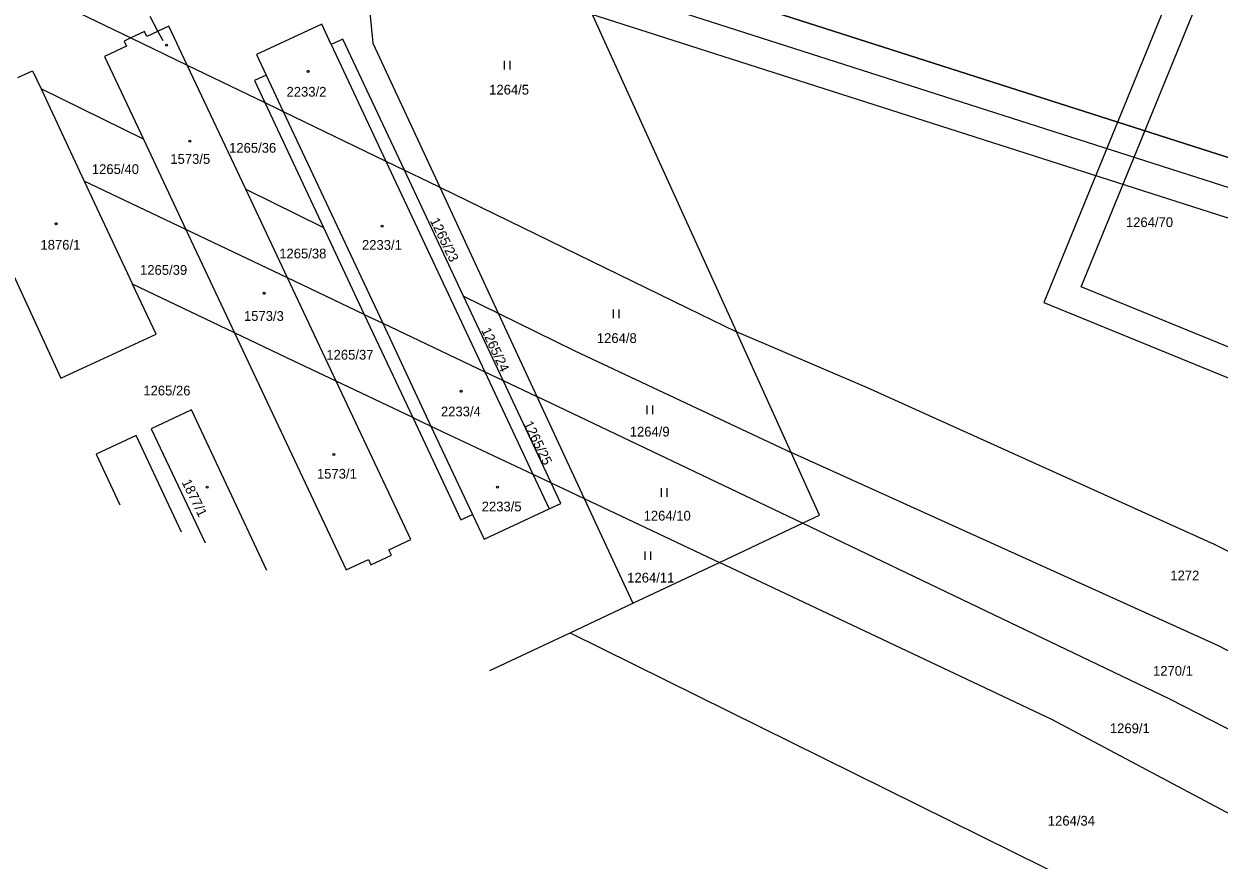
# Model space of a CAD drawing. Extents: x -779330 to -774454, y -1144748 to -1142831.
# Drawn here: x -777170.1 to -776961.8, y -1144133.7 to -1143987.9 of the extents above; entities that cross this region are included whole.
import ezdxf

# ---------------------------------------------------------------- set-up
doc = ezdxf.new("R2010")
doc.units = 0
for name, color, linetype in [('Hranice parcel', 7, 'Continuous'), ('Parcelní čísla', 7, 'Continuous'), ('Pop  PČ popisy', 7, 'Continuous'), ('Vnitřní kresba', 7, 'Continuous'), ('Vrstva 1', 7, 'Continuous'), ('Značky budov', 7, 'Continuous'), ('Značky kultur', 7, 'Continuous')]:
    doc.layers.add(name, color=color, linetype=linetype)

msp = doc.modelspace()

# ---------------------------------------------------------------- linework, layer by layer
at = {"layer": 'Hranice parcel'}
for p, q in [((-777087.76, -1143949.47), (-777045.94, -1144041.58)), ((-777151.49, -1143990.35), (-777141.63, -1143995.11)), ((-777141.63, -1143995.11), (-777128.13, -1144001.62)), ((-777131.43, -1144016.75), (-777141.63, -1143995.11)), ((-777149.29, -1144007.99), (-777167.13, -1143999.23)), ((-777167.13, -1143999.23), (-777159.6, -1144015.3)), ((-777128.13, -1144001.62), (-777117.9, -1144023.39)), ((-777149.29, -1144007.99), (-777141.88, -1144023.74)), ((-777093.49, -1144035.37), (-777103.79, -1144013.4)), ((-777141.88, -1144023.74), (-777159.6, -1144015.3)), ((-777159.6, -1144015.3), (-777151.17, -1144033.27)), ((-777131.43, -1144016.75), (-777117.9, -1144023.39)), ((-777124.16, -1144032.18), (-777131.43, -1144016.75)), ((-777097.63, -1144016.39), (-777087.44, -1144038.34)), ((-777141.88, -1144023.74), (-777133.39, -1144041.77)), ((-777124.16, -1144032.18), (-777141.88, -1144023.74)), ((-777117.9, -1144023.39), (-777110.78, -1144038.56)), ((-777110.78, -1144038.56), (-777124.16, -1144032.18)), ((-777115.67, -1144050.19), (-777124.16, -1144032.18)), ((-777133.39, -1144041.77), (-777151.17, -1144033.27)), ((-777093.49, -1144035.37), (-777087.44, -1144038.34)), ((-777086.6, -1144050.07), (-777093.49, -1144035.37)), ((-777087.44, -1144038.34), (-777080.69, -1144052.88)), ((-777110.78, -1144038.56), (-777102.35, -1144056.49)), ((-777036.4, -1144062.59), (-777045.94, -1144041.58)), ((-777102.35, -1144056.49), (-777115.67, -1144050.19)), ((-777078.24, -1144067.9), (-777086.6, -1144050.07)), ((-777086.6, -1144050.07), (-777080.69, -1144052.88)), ((-777034.39, -1144074.95), (-777080.69, -1144052.88)), ((-777080.69, -1144052.88), (-777072.46, -1144070.64)), ((-777078.24, -1144067.9), (-777072.46, -1144070.64)), ((-777072.46, -1144070.64), (-777048.9, -1144081.78)), ((-777072.46, -1144070.64), (-777063.99, -1144088.88)), ((-777048.9, -1144081.78), (-777034.39, -1144074.95)), ((-777063.99, -1144088.88), (-777048.9, -1144081.78)), ((-777074.93, -1144094.03), (-777063.99, -1144088.88)), ((-777088.89, -1144100.6), (-777074.93, -1144094.03))]:
    msp.add_line(p, q, dxfattribs=at)
for points in [[(-777242.24, -1143946.21), (-777233.61, -1143950.34), (-777182.11, -1143975.59), (-777151.49, -1143990.35)], [(-777093.52, -1143952.82), (-777109.82, -1143985.95), (-777109.29, -1143991.28), (-777097.63, -1144016.39)], [(-777141.63, -1143995.11), (-777144.83, -1143988.32), (-777148.68, -1143990.13), (-777149.1, -1143989.23), (-777151.49, -1143990.35)], [(-777103.79, -1144013.4), (-777114.5, -1143990.57), (-777116.54, -1143991.53), (-777118.21, -1143987.96), (-777129.57, -1143993.28), (-777127.9, -1143996.84), (-777129.93, -1143997.79), (-777128.13, -1144001.62)], [(-777151.49, -1143990.35), (-777152.65, -1143990.9), (-777152.22, -1143991.8), (-777156.06, -1143993.61), (-777149.29, -1144007.99)], [(-777171.18, -1143997.24), (-777168.61, -1143996.07), (-777167.13, -1143999.23)], [(-777128.13, -1144001.62), (-777125.96, -1144002.66), (-777124.93, -1144003.16), (-777107.02, -1144011.84), (-777103.79, -1144013.4)], [(-777103.79, -1144013.4), (-777099.68, -1144015.4), (-777097.63, -1144016.39)], [(-777097.63, -1144016.39), (-777054.51, -1144037.4), (-777045.94, -1144041.58)], [(-777176.95, -1144020.96), (-777163.68, -1144049.68), (-777147.08, -1144042), (-777151.17, -1144033.27)], [(-777087.44, -1144038.34), (-777074.06, -1144044.91), (-777036.4, -1144062.59)], [(-777110.78, -1144038.56), (-777107.58, -1144040.08), (-777089.79, -1144048.55), (-777086.6, -1144050.07)], [(-777115.67, -1144050.19), (-777124.3, -1144046.11), (-777133.39, -1144041.77)], [(-777133.39, -1144041.77), (-777113.94, -1144083.08), (-777110.04, -1144081.26), (-777109.62, -1144082.17), (-777106.05, -1144080.5), (-777106.48, -1144079.59), (-777102.66, -1144077.8), (-777115.67, -1144050.19)], [(-776908.05, -1144105.74), (-776962.58, -1144078.67), (-777023.09, -1144051.34), (-777045.94, -1144041.58)], [(-777127.79, -1144083.17), (-777140.89, -1144055.19), (-777147.92, -1144058.49), (-777138.54, -1144078.35)], [(-777102.35, -1144056.49), (-777099.16, -1144058), (-777081.43, -1144066.39), (-777078.24, -1144067.9)], [(-777102.35, -1144056.49), (-777093.95, -1144074.37), (-777091.92, -1144073.41), (-777089.88, -1144077.75), (-777078.58, -1144072.46), (-777076.55, -1144071.5), (-777078.24, -1144067.9)], [(-777142.67, -1144076.5), (-777150.56, -1144059.63), (-777157.5, -1144062.89), (-777153.38, -1144071.71)], [(-777034.39, -1144074.95), (-777031.42, -1144073.55), (-777036.4, -1144062.59)], [(-776898.22, -1144129.38), (-776961.92, -1144096.33), (-777036.4, -1144062.59)], [(-776903.59, -1144139.82), (-776970.41, -1144105.59), (-777034.39, -1144074.95)], [(-776910.86, -1144151.74), (-776990.98, -1144109.17), (-777048.9, -1144081.78)], [(-777074.93, -1144094.03), (-776915.07, -1144173.12), (-776914.76, -1144172.32)]]:
    msp.add_lwpolyline(points, dxfattribs=at)
at = {"layer": 'Pop  PČ popisy'}
for p, q in [((-777146.69, -1143989.28), (-777148.1, -1143986.63)), ((-777145.84, -1143990.86), (-777146.69, -1143989.28))]:
    msp.add_line(p, q, dxfattribs=at)
at = {"layer": 'Vnitřní kresba'}
for p, q in [((-777116.54, -1143991.53), (-777107.02, -1144011.84)), ((-777127.9, -1143996.84), (-777124.93, -1144003.16)), ((-777124.93, -1144003.16), (-777107.58, -1144040.08)), ((-777107.02, -1144011.84), (-777089.79, -1144048.55)), ((-777107.58, -1144040.08), (-777099.16, -1144058)), ((-777089.79, -1144048.55), (-777081.43, -1144066.39)), ((-777099.16, -1144058), (-777091.92, -1144073.41)), ((-777081.43, -1144066.39), (-777078.58, -1144072.46))]:
    msp.add_line(p, q, dxfattribs=at)
at = {"layer": 'Vrstva 1'}
for points in [[(-776606.88, -1143822.95), (-777806.9, -1143438.86), (-777897.43, -1143721.71), (-776697.42, -1144105.81)], [(-776700.65, -1144099.52), (-777891.15, -1143718.47), (-777803.66, -1143445.14), (-776613.17, -1143826.19)], [(-776619.45, -1143829.42), (-777605.19, -1143513.91), (-777689.63, -1143777.73), (-776703.89, -1144093.24)], [(-776703.89, -1144093.24), (-777689.63, -1143777.73), (-777605.19, -1143513.91), (-776619.45, -1143829.42)], [(-775713.68, -1144238.31), (-776879.99, -1143761.57), (-776992.36, -1144036.48), (-775826.05, -1144513.22)], [(-775828.78, -1144506.7), (-776985.84, -1144033.74), (-776877.25, -1143768.09), (-775720.2, -1144241.05)]]:
    msp.add_lwpolyline(points, close=True, dxfattribs=at)
at = {"layer": 'Značky budov'}
for centre in [(-777145.26, -1143991.64), (-777120.57, -1143996.19), (-777141.17, -1144008.34), (-777164.48, -1144022.74), (-777107.69, -1144023.16), (-777128.24, -1144034.87), (-777093.9, -1144051.95), (-777116.1, -1144062.96), (-777138.16, -1144068.65), (-777087.55, -1144068.67)]:
    msp.add_circle(centre, 0.175, dxfattribs=at)
at = {"layer": 'Značky kultur'}
for p, q in [((-777086.37, -1143995.84), (-777086.37, -1143994.34)), ((-777085.37, -1143995.84), (-777085.37, -1143994.34)), ((-777067.34, -1144039.19), (-777067.34, -1144037.69)), ((-777066.34, -1144039.19), (-777066.34, -1144037.69)), ((-777061.51, -1144055.92), (-777061.51, -1144054.42)), ((-777060.51, -1144055.92), (-777060.51, -1144054.42)), ((-777058.97, -1144070.35), (-777058.97, -1144068.85)), ((-777057.97, -1144070.35), (-777057.97, -1144068.85)), ((-777061.84, -1144081.35), (-777061.84, -1144079.85)), ((-777060.84, -1144081.35), (-777060.84, -1144079.85))]:
    msp.add_line(p, q, dxfattribs=at)

# ---------------------------------------------------------------- texts
at = {"layer": 'Parcelní čísla'}
for s, p in [('2233/2', (-777124.34, -1144000.6)), ('1264/5', (-777089.02, -1144000.23)), ('1265/36', (-777134.35, -1144010.37)), ('1573/5', (-777144.59, -1144012.31)), ('1265/40', (-777158.27, -1144014.08)), ('1264/70', (-776978.04, -1144023.33)), ('1876/1', (-777167.23, -1144027.27)), ('2233/1', (-777111.19, -1144027.29)), ('1265/38', (-777125.61, -1144028.79)), ('1265/39', (-777149.87, -1144031.65)), ('1573/3', (-777131.76, -1144039.67)), ('1264/8', (-777070.25, -1144043.53)), ('1265/37', (-777117.4, -1144046.43)), ('1265/26', (-777149.3, -1144052.67)), ('2233/4', (-777097.43, -1144056.32)), ('1264/9', (-777064.52, -1144059.83)), ('1573/1', (-777119.04, -1144067.17)), ('2233/5', (-777090.32, -1144072.88)), ('1264/10', (-777062.1, -1144074.48)), ('1264/11', (-777064.96, -1144085.28)), ('1272', (-776970.3, -1144084.9)), ('1270/1', (-776973.32, -1144101.52)), ('1269/1', (-776980.83, -1144111.53)), ('1264/34', (-776991.65, -1144127.65))]:
    msp.add_text(s, height=1.7, dxfattribs=at).set_placement(p)
for s, rotation, p in [('1265/23', 296, (-777099.38, -1144022.21)), ('1265/24', 295, (-777090.44, -1144041.31)), ('1265/25', 296, (-777083.09, -1144057.61)), ('1877/1', 296, (-777142.65, -1144067.78))]:
    msp.add_text(s, height=1.7, rotation=rotation, dxfattribs=at).set_placement(p)

doc.saveas('drawing.dxf')
